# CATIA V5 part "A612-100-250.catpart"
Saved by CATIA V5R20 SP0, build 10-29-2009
Part number: A612-100-250
Source: Unknown
Property "A": "30.000"
Property "ARTICLENO": "A612-100-250"
Property "B": "40.000"
Property "BOMINFO": "A612-100-250"
Property "CODE": "A612-100-250"
Property "D": "17.500"
Property "FORM": "B"
Property "L": "250.000"
Property "L1": "45.000"
Property "L2": "80.000"
Property "L3": "0.000"
Property "LINA": "A612-100-250"
Property "NB": "A612-100-250"
Property "NBSYN": "$CODE."
Property "NN": "A612"
Property "NT": "CDI 3357 E-Type Wear Plates, steel and self-lubricating"
Property "SUPPLIER": "CF"
Property "T": "25.000"
Property "W": "100.000"
Bounding box of the stored display mesh (mm): x 0 to 25, y 0 to 250, z 0 to 100
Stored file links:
  C:\Users\Utente\Desktop\3D files A612\A612-100-250.catpart
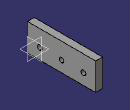
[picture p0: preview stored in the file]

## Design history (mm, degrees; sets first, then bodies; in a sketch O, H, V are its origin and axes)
Body1 "Geometry.1" (main body)
  Solid1 "A612-100-250.catpart": solid without history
